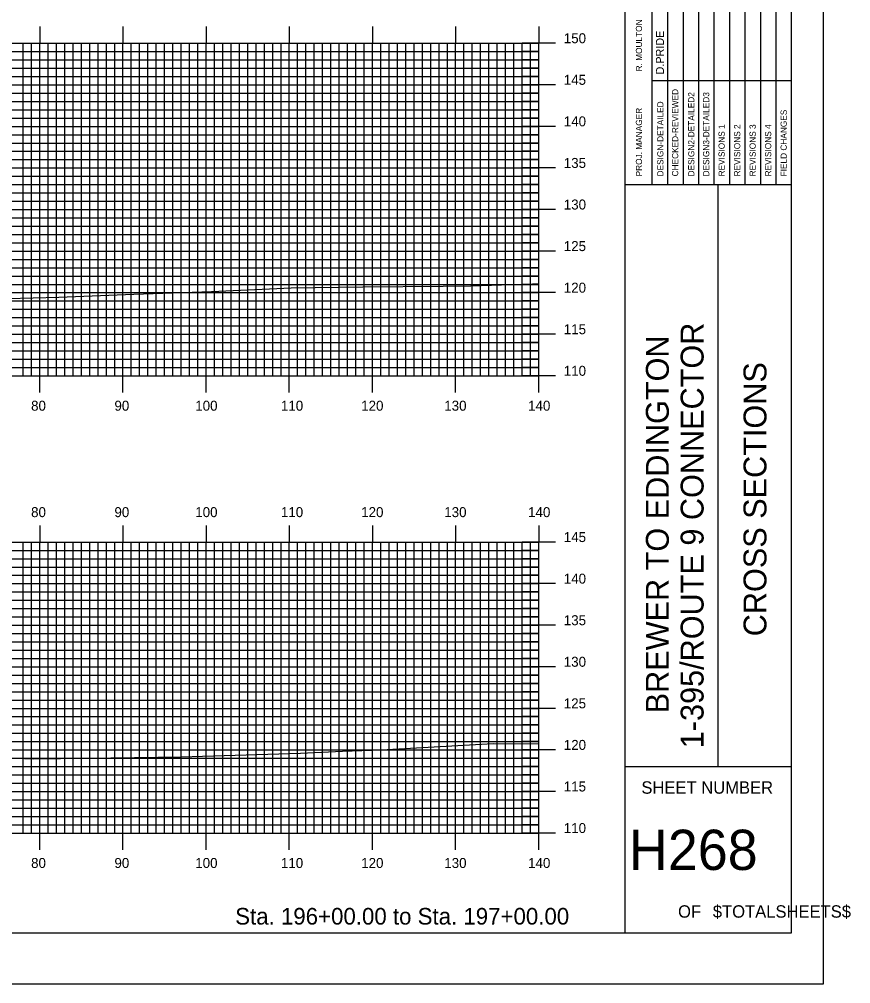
# Model space of a CAD drawing. Extents: x 1789730 to 1790074, y 442591 to 442811.
# Drawn here: x 1789973.7 to 1790073.7, y 442590.5 to 442706.6 of the extents above; entities that cross this region are included whole.
import ezdxf

# ---------------------------------------------------------------- set-up
doc = ezdxf.new("R2010")
doc.units = 0
for name, color, linetype in [('BORDER', 7, 'Continuous'), ('H_V ANNOTATION', 7, 'Continuous'), ('MAJOR', 7, 'Continuous'), ('MINOR', 7, 'Continuous'), ('PLOT BOUNDARY', 7, 'Continuous'), ('S_Roadway_Centerline', 7, 'Continuous')]:
    doc.layers.add(name, color=color, linetype=linetype)

msp = doc.modelspace()

# ---------------------------------------------------------------- linework, layer by layer
at = {"layer": 'BORDER'}
for p, q in [((1790046.58, 442596.67), (1790046.58, 442806.67)), ((1790046.58, 442686.67), (1790066.58, 442686.67)), ((1790057.76, 442616.67), (1790057.76, 442686.67)), ((1790046.58, 442616.67), (1790066.58, 442616.67))]:
    msp.add_line(p, q, dxfattribs=at)
msp.add_lwpolyline([(1789746.58, 442596.67), (1790066.58, 442596.67), (1790066.58, 442806.67), (1789746.58, 442806.67)], close=True, dxfattribs=at)
for points in [[(1790051.68, 442686.68), (1790051.68, 442721.67)], [(1790053.54, 442721.67), (1790053.54, 442686.68)], [(1790055.4, 442686.68), (1790055.4, 442721.67)], [(1790057.27, 442686.68), (1790057.27, 442721.67)], [(1790059.13, 442686.68), (1790059.13, 442721.67)], [(1790060.99, 442686.68), (1790060.99, 442721.67)], [(1790062.86, 442686.68), (1790062.86, 442721.67)], [(1790064.72, 442686.68), (1790064.72, 442721.67)], [(1790049.81, 442686.68), (1790049.81, 442720.26)], [(1790049.81, 442699.17), (1790066.58, 442699.17)]]:
    msp.add_lwpolyline(points, dxfattribs=at)
at = {"layer": 'MAJOR'}
for p, q in [((1789976.18, 442705.67), (1789976.18, 442703.67)), ((1789986.18, 442705.67), (1789986.18, 442703.67)), ((1789996.18, 442705.67), (1789996.18, 442703.67)), ((1790006.18, 442705.67), (1790006.18, 442703.67)), ((1790016.18, 442705.67), (1790016.18, 442703.67)), ((1790026.18, 442705.67), (1790026.18, 442703.67)), ((1790036.18, 442705.67), (1790036.18, 442703.67)), ((1789756.18, 442703.67), (1790036.18, 442703.67)), ((1789756.18, 442703.67), (1790036.18, 442703.67)), ((1789976.18, 442663.67), (1789976.18, 442703.67)), ((1789986.18, 442663.67), (1789986.18, 442703.67)), ((1789996.18, 442663.67), (1789996.18, 442703.67)), ((1790006.18, 442663.67), (1790006.18, 442703.67)), ((1790016.18, 442663.67), (1790016.18, 442703.67)), ((1790026.18, 442663.67), (1790026.18, 442703.67)), ((1790038.19, 442703.67), (1790034.18, 442703.67)), ((1790036.18, 442663.67), (1790036.18, 442703.67)), ((1790036.18, 442663.67), (1790036.18, 442703.67)), ((1789756.18, 442698.67), (1790036.18, 442698.67)), ((1790038.19, 442698.67), (1790034.18, 442698.67)), ((1789756.18, 442693.67), (1790036.18, 442693.67)), ((1790038.19, 442693.67), (1790034.18, 442693.67)), ((1789756.18, 442688.67), (1790036.18, 442688.67)), ((1790038.19, 442688.67), (1790034.18, 442688.67)), ((1789756.18, 442683.67), (1790036.18, 442683.67)), ((1790038.19, 442683.67), (1790034.18, 442683.67)), ((1789756.18, 442678.67), (1790036.18, 442678.67)), ((1790038.19, 442678.67), (1790034.18, 442678.67)), ((1789756.18, 442673.67), (1790036.18, 442673.67)), ((1790038.19, 442673.67), (1790034.18, 442673.67)), ((1789756.18, 442668.67), (1790036.18, 442668.67)), ((1790038.19, 442668.67), (1790034.18, 442668.67)), ((1789756.18, 442663.67), (1790036.18, 442663.67)), ((1789756.18, 442663.67), (1790036.18, 442663.67)), ((1789976.18, 442661.66), (1789976.18, 442663.67)), ((1789986.18, 442661.66), (1789986.18, 442663.67)), ((1789996.18, 442661.66), (1789996.18, 442663.67)), ((1790006.18, 442661.66), (1790006.18, 442663.67)), ((1790016.18, 442661.66), (1790016.18, 442663.67)), ((1790026.18, 442661.66), (1790026.18, 442663.67)), ((1790038.19, 442663.67), (1790034.18, 442663.67)), ((1790036.18, 442661.66), (1790036.18, 442663.67)), ((1789976.18, 442645.67), (1789976.18, 442643.67)), ((1789986.18, 442645.67), (1789986.18, 442643.67)), ((1789996.18, 442645.67), (1789996.18, 442643.67)), ((1790006.18, 442645.67), (1790006.18, 442643.67)), ((1790016.18, 442645.67), (1790016.18, 442643.67)), ((1790026.18, 442645.67), (1790026.18, 442643.67)), ((1790036.18, 442645.67), (1790036.18, 442643.67)), ((1789756.18, 442643.67), (1790036.18, 442643.67)), ((1789756.18, 442643.67), (1790036.18, 442643.67)), ((1789976.18, 442608.67), (1789976.18, 442643.67)), ((1789986.18, 442608.67), (1789986.18, 442643.67)), ((1789996.18, 442608.67), (1789996.18, 442643.67)), ((1790006.18, 442608.67), (1790006.18, 442643.67)), ((1790016.18, 442608.67), (1790016.18, 442643.67)), ((1790026.18, 442608.67), (1790026.18, 442643.67)), ((1790038.19, 442643.67), (1790034.18, 442643.67)), ((1790036.18, 442608.67), (1790036.18, 442643.67)), ((1790036.18, 442608.67), (1790036.18, 442643.67)), ((1789756.18, 442638.67), (1790036.18, 442638.67)), ((1790038.19, 442638.67), (1790034.18, 442638.67)), ((1789756.18, 442633.67), (1790036.18, 442633.67)), ((1790038.19, 442633.67), (1790034.18, 442633.67)), ((1789756.18, 442628.67), (1790036.18, 442628.67)), ((1790038.19, 442628.67), (1790034.18, 442628.67)), ((1789756.18, 442623.67), (1790036.18, 442623.67)), ((1790038.19, 442623.67), (1790034.18, 442623.67)), ((1789756.18, 442618.67), (1790036.18, 442618.67)), ((1790038.19, 442618.67), (1790034.18, 442618.67)), ((1789756.18, 442613.67), (1790036.18, 442613.67)), ((1790038.19, 442613.67), (1790034.18, 442613.67)), ((1789756.18, 442608.67), (1790036.18, 442608.67)), ((1789756.18, 442608.67), (1790036.18, 442608.67)), ((1789976.18, 442606.66), (1789976.18, 442608.67)), ((1789986.18, 442606.66), (1789986.18, 442608.67)), ((1789996.18, 442606.66), (1789996.18, 442608.67)), ((1790006.18, 442606.66), (1790006.18, 442608.67)), ((1790016.18, 442606.66), (1790016.18, 442608.67)), ((1790026.18, 442606.66), (1790026.18, 442608.67)), ((1790038.19, 442608.67), (1790034.18, 442608.67)), ((1790036.18, 442606.66), (1790036.18, 442608.67))]:
    msp.add_line(p, q, dxfattribs=at)
at = {"layer": 'MINOR'}
for p, q in [((1789974.18, 442663.67), (1789974.18, 442703.67)), ((1789975.18, 442663.67), (1789975.18, 442703.67)), ((1789977.18, 442663.67), (1789977.18, 442703.67)), ((1789978.18, 442663.67), (1789978.18, 442703.67)), ((1789979.18, 442663.67), (1789979.18, 442703.67)), ((1789980.18, 442663.67), (1789980.18, 442703.67)), ((1789981.18, 442663.67), (1789981.18, 442703.67)), ((1789982.18, 442663.67), (1789982.18, 442703.67)), ((1789983.18, 442663.67), (1789983.18, 442703.67)), ((1789984.18, 442663.67), (1789984.18, 442703.67)), ((1789985.18, 442663.67), (1789985.18, 442703.67)), ((1789987.18, 442663.67), (1789987.18, 442703.67)), ((1789988.18, 442663.67), (1789988.18, 442703.67)), ((1789989.18, 442663.67), (1789989.18, 442703.67)), ((1789990.18, 442663.67), (1789990.18, 442703.67)), ((1789991.18, 442663.67), (1789991.18, 442703.67)), ((1789992.18, 442663.67), (1789992.18, 442703.67)), ((1789993.18, 442663.67), (1789993.18, 442703.67)), ((1789994.18, 442663.67), (1789994.18, 442703.67)), ((1789995.18, 442663.67), (1789995.18, 442703.67)), ((1789997.18, 442663.67), (1789997.18, 442703.67)), ((1789998.18, 442663.67), (1789998.18, 442703.67)), ((1789999.18, 442663.67), (1789999.18, 442703.67)), ((1790000.18, 442663.67), (1790000.18, 442703.67)), ((1790001.18, 442663.67), (1790001.18, 442703.67)), ((1790002.18, 442663.67), (1790002.18, 442703.67)), ((1790003.18, 442663.67), (1790003.18, 442703.67)), ((1790004.18, 442663.67), (1790004.18, 442703.67)), ((1790005.18, 442663.67), (1790005.18, 442703.67)), ((1790007.18, 442663.67), (1790007.18, 442703.67)), ((1790008.18, 442663.67), (1790008.18, 442703.67)), ((1790009.18, 442663.67), (1790009.18, 442703.67)), ((1790010.18, 442663.67), (1790010.18, 442703.67)), ((1790011.18, 442663.67), (1790011.18, 442703.67)), ((1790012.18, 442663.67), (1790012.18, 442703.67)), ((1790013.18, 442663.67), (1790013.18, 442703.67)), ((1790014.18, 442663.67), (1790014.18, 442703.67)), ((1790015.18, 442663.67), (1790015.18, 442703.67)), ((1790017.18, 442663.67), (1790017.18, 442703.67)), ((1790018.18, 442663.67), (1790018.18, 442703.67)), ((1790019.18, 442663.67), (1790019.18, 442703.67)), ((1790020.18, 442663.67), (1790020.18, 442703.67)), ((1790021.18, 442663.67), (1790021.18, 442703.67)), ((1790022.18, 442663.67), (1790022.18, 442703.67)), ((1790023.18, 442663.67), (1790023.18, 442703.67)), ((1790024.18, 442663.67), (1790024.18, 442703.67)), ((1790025.18, 442663.67), (1790025.18, 442703.67)), ((1790027.18, 442663.67), (1790027.18, 442703.67)), ((1790028.18, 442663.67), (1790028.18, 442703.67)), ((1790029.18, 442663.67), (1790029.18, 442703.67)), ((1790030.18, 442663.67), (1790030.18, 442703.67)), ((1790031.18, 442663.67), (1790031.18, 442703.67)), ((1790032.18, 442663.67), (1790032.18, 442703.67)), ((1790033.18, 442663.67), (1790033.18, 442703.67)), ((1790034.18, 442663.67), (1790034.18, 442703.67)), ((1790035.18, 442663.67), (1790035.18, 442703.67)), ((1789756.18, 442702.67), (1790036.18, 442702.67)), ((1790036.18, 442702.67), (1790034.18, 442702.67)), ((1789756.18, 442701.67), (1790036.18, 442701.67)), ((1789756.18, 442700.67), (1790036.18, 442700.67)), ((1790036.18, 442701.67), (1790034.18, 442701.67)), ((1790036.18, 442700.67), (1790034.18, 442700.67)), ((1789756.18, 442699.67), (1790036.18, 442699.67)), ((1790036.18, 442699.67), (1790034.18, 442699.67)), ((1789756.18, 442697.67), (1790036.18, 442697.67)), ((1790036.18, 442697.67), (1790034.18, 442697.67)), ((1789756.18, 442696.67), (1790036.18, 442696.67)), ((1790036.18, 442696.67), (1790034.18, 442696.67)), ((1789756.18, 442695.67), (1790036.18, 442695.67)), ((1790036.18, 442695.67), (1790034.18, 442695.67)), ((1789756.18, 442694.67), (1790036.18, 442694.67)), ((1790036.18, 442694.67), (1790034.18, 442694.67)), ((1789756.18, 442692.67), (1790036.18, 442692.67)), ((1790036.18, 442692.67), (1790034.18, 442692.67)), ((1789756.18, 442691.67), (1790036.18, 442691.67)), ((1790036.18, 442691.67), (1790034.18, 442691.67)), ((1789756.18, 442690.67), (1790036.18, 442690.67)), ((1790036.18, 442690.67), (1790034.18, 442690.67)), ((1789756.18, 442689.67), (1790036.18, 442689.67)), ((1790036.18, 442689.67), (1790034.18, 442689.67)), ((1789756.18, 442687.67), (1790036.18, 442687.67)), ((1790036.18, 442687.67), (1790034.18, 442687.67)), ((1789756.18, 442686.67), (1790036.18, 442686.67)), ((1789756.18, 442685.67), (1790036.18, 442685.67)), ((1790036.18, 442686.67), (1790034.18, 442686.67)), ((1790036.18, 442685.67), (1790034.18, 442685.67)), ((1789756.18, 442684.67), (1790036.18, 442684.67)), ((1790036.18, 442684.67), (1790034.18, 442684.67)), ((1789756.18, 442682.67), (1790036.18, 442682.67)), ((1790036.18, 442682.67), (1790034.18, 442682.67)), ((1789756.18, 442681.67), (1790036.18, 442681.67)), ((1790036.18, 442681.67), (1790034.18, 442681.67)), ((1789756.18, 442680.67), (1790036.18, 442680.67)), ((1790036.18, 442680.67), (1790034.18, 442680.67)), ((1789756.18, 442679.67), (1790036.18, 442679.67)), ((1790036.18, 442679.67), (1790034.18, 442679.67)), ((1789756.18, 442677.67), (1790036.18, 442677.67)), ((1790036.18, 442677.67), (1790034.18, 442677.67)), ((1789756.18, 442676.67), (1790036.18, 442676.67)), ((1790036.18, 442676.67), (1790034.18, 442676.67)), ((1789756.18, 442675.67), (1790036.18, 442675.67)), ((1790036.18, 442675.67), (1790034.18, 442675.67)), ((1789756.18, 442674.67), (1790036.18, 442674.67)), ((1790036.18, 442674.67), (1790034.18, 442674.67)), ((1789756.18, 442672.67), (1790036.18, 442672.67)), ((1789756.18, 442671.67), (1790036.18, 442671.67)), ((1790036.18, 442672.67), (1790034.18, 442672.67)), ((1790036.18, 442671.67), (1790034.18, 442671.67)), ((1789756.18, 442670.67), (1790036.18, 442670.67)), ((1790036.18, 442670.67), (1790034.18, 442670.67)), ((1789756.18, 442669.67), (1790036.18, 442669.67)), ((1790036.18, 442669.67), (1790034.18, 442669.67)), ((1789756.18, 442667.67), (1790036.18, 442667.67)), ((1790036.18, 442667.67), (1790034.18, 442667.67)), ((1789756.18, 442666.67), (1790036.18, 442666.67)), ((1790036.18, 442666.67), (1790034.18, 442666.67)), ((1789756.18, 442665.67), (1790036.18, 442665.67)), ((1789756.18, 442664.67), (1790036.18, 442664.67)), ((1790036.18, 442665.67), (1790034.18, 442665.67)), ((1790036.18, 442664.67), (1790034.18, 442664.67)), ((1789756.18, 442642.67), (1790036.18, 442642.67)), ((1789974.18, 442608.67), (1789974.18, 442643.67)), ((1789975.18, 442608.67), (1789975.18, 442643.67)), ((1789977.18, 442608.67), (1789977.18, 442643.67)), ((1789978.18, 442608.67), (1789978.18, 442643.67)), ((1789979.18, 442608.67), (1789979.18, 442643.67)), ((1789980.18, 442608.67), (1789980.18, 442643.67)), ((1789981.18, 442608.67), (1789981.18, 442643.67)), ((1789982.18, 442608.67), (1789982.18, 442643.67)), ((1789983.18, 442608.67), (1789983.18, 442643.67)), ((1789984.18, 442608.67), (1789984.18, 442643.67)), ((1789985.18, 442608.67), (1789985.18, 442643.67)), ((1789987.18, 442608.67), (1789987.18, 442643.67)), ((1789988.18, 442608.67), (1789988.18, 442643.67)), ((1789989.18, 442608.67), (1789989.18, 442643.67)), ((1789990.18, 442608.67), (1789990.18, 442643.67)), ((1789991.18, 442608.67), (1789991.18, 442643.67)), ((1789992.18, 442608.67), (1789992.18, 442643.67)), ((1789993.18, 442608.67), (1789993.18, 442643.67)), ((1789994.18, 442608.67), (1789994.18, 442643.67)), ((1789995.18, 442608.67), (1789995.18, 442643.67)), ((1789997.18, 442608.67), (1789997.18, 442643.67)), ((1789998.18, 442608.67), (1789998.18, 442643.67)), ((1789999.18, 442608.67), (1789999.18, 442643.67)), ((1790000.18, 442608.67), (1790000.18, 442643.67)), ((1790001.18, 442608.67), (1790001.18, 442643.67)), ((1790002.18, 442608.67), (1790002.18, 442643.67)), ((1790003.18, 442608.67), (1790003.18, 442643.67)), ((1790004.18, 442608.67), (1790004.18, 442643.67)), ((1790005.18, 442608.67), (1790005.18, 442643.67)), ((1790007.18, 442608.67), (1790007.18, 442643.67)), ((1790008.18, 442608.67), (1790008.18, 442643.67)), ((1790009.18, 442608.67), (1790009.18, 442643.67)), ((1790010.18, 442608.67), (1790010.18, 442643.67)), ((1790011.18, 442608.67), (1790011.18, 442643.67)), ((1790012.18, 442608.67), (1790012.18, 442643.67)), ((1790013.18, 442608.67), (1790013.18, 442643.67)), ((1790014.18, 442608.67), (1790014.18, 442643.67)), ((1790015.18, 442608.67), (1790015.18, 442643.67)), ((1790017.18, 442608.67), (1790017.18, 442643.67)), ((1790018.18, 442608.67), (1790018.18, 442643.67)), ((1790019.18, 442608.67), (1790019.18, 442643.67)), ((1790020.18, 442608.67), (1790020.18, 442643.67)), ((1790021.18, 442608.67), (1790021.18, 442643.67)), ((1790022.18, 442608.67), (1790022.18, 442643.67)), ((1790023.18, 442608.67), (1790023.18, 442643.67)), ((1790024.18, 442608.67), (1790024.18, 442643.67)), ((1790025.18, 442608.67), (1790025.18, 442643.67)), ((1790027.18, 442608.67), (1790027.18, 442643.67)), ((1790028.18, 442608.67), (1790028.18, 442643.67)), ((1790029.18, 442608.67), (1790029.18, 442643.67)), ((1790030.18, 442608.67), (1790030.18, 442643.67)), ((1790031.18, 442608.67), (1790031.18, 442643.67)), ((1790032.18, 442608.67), (1790032.18, 442643.67)), ((1790033.18, 442608.67), (1790033.18, 442643.67)), ((1790034.18, 442608.67), (1790034.18, 442643.67)), ((1790036.18, 442642.67), (1790034.18, 442642.67)), ((1790035.18, 442608.67), (1790035.18, 442643.67)), ((1789756.18, 442641.67), (1790036.18, 442641.67)), ((1790036.18, 442641.67), (1790034.18, 442641.67)), ((1789756.18, 442640.67), (1790036.18, 442640.67)), ((1790036.18, 442640.67), (1790034.18, 442640.67)), ((1789756.18, 442639.67), (1790036.18, 442639.67)), ((1790036.18, 442639.67), (1790034.18, 442639.67)), ((1789756.18, 442637.67), (1790036.18, 442637.67)), ((1790036.18, 442637.67), (1790034.18, 442637.67)), ((1789756.18, 442636.67), (1790036.18, 442636.67)), ((1789756.18, 442635.67), (1790036.18, 442635.67)), ((1790036.18, 442636.67), (1790034.18, 442636.67)), ((1790036.18, 442635.67), (1790034.18, 442635.67)), ((1789756.18, 442634.67), (1790036.18, 442634.67)), ((1790036.18, 442634.67), (1790034.18, 442634.67)), ((1789756.18, 442632.67), (1790036.18, 442632.67)), ((1790036.18, 442632.67), (1790034.18, 442632.67)), ((1789756.18, 442631.67), (1790036.18, 442631.67)), ((1790036.18, 442631.67), (1790034.18, 442631.67)), ((1789756.18, 442630.67), (1790036.18, 442630.67)), ((1790036.18, 442630.67), (1790034.18, 442630.67)), ((1789756.18, 442629.67), (1790036.18, 442629.67)), ((1790036.18, 442629.67), (1790034.18, 442629.67)), ((1789756.18, 442627.67), (1790036.18, 442627.67)), ((1790036.18, 442627.67), (1790034.18, 442627.67)), ((1789756.18, 442626.67), (1790036.18, 442626.67)), ((1790036.18, 442626.67), (1790034.18, 442626.67)), ((1789756.18, 442625.67), (1790036.18, 442625.67)), ((1790036.18, 442625.67), (1790034.18, 442625.67)), ((1789756.18, 442624.67), (1790036.18, 442624.67)), ((1790036.18, 442624.67), (1790034.18, 442624.67)), ((1789756.18, 442622.67), (1790036.18, 442622.67)), ((1790036.18, 442622.67), (1790034.18, 442622.67)), ((1789756.18, 442621.67), (1790036.18, 442621.67)), ((1789756.18, 442620.67), (1790036.18, 442620.67)), ((1790036.18, 442621.67), (1790034.18, 442621.67)), ((1790036.18, 442620.67), (1790034.18, 442620.67)), ((1789756.18, 442619.67), (1790036.18, 442619.67)), ((1790036.18, 442619.67), (1790034.18, 442619.67)), ((1789756.18, 442617.67), (1790036.18, 442617.67)), ((1790036.18, 442617.67), (1790034.18, 442617.67)), ((1789756.18, 442616.67), (1790036.18, 442616.67)), ((1790036.18, 442616.67), (1790034.18, 442616.67)), ((1789756.18, 442615.67), (1790036.18, 442615.67)), ((1790036.18, 442615.67), (1790034.18, 442615.67)), ((1789756.18, 442614.67), (1790036.18, 442614.67)), ((1790036.18, 442614.67), (1790034.18, 442614.67)), ((1789756.18, 442612.67), (1790036.18, 442612.67)), ((1790036.18, 442612.67), (1790034.18, 442612.67)), ((1789756.18, 442611.67), (1790036.18, 442611.67)), ((1790036.18, 442611.67), (1790034.18, 442611.67)), ((1789756.18, 442610.67), (1790036.18, 442610.67)), ((1790036.18, 442610.67), (1790034.18, 442610.67)), ((1789756.18, 442609.67), (1790036.18, 442609.67)), ((1790036.18, 442609.67), (1790034.18, 442609.67))]:
    msp.add_line(p, q, dxfattribs=at)
at = {"layer": 'PLOT BOUNDARY'}
msp.add_lwpolyline([(1789730.4, 442590.55), (1790070.4, 442590.55), (1790070.4, 442810.55), (1789730.4, 442810.55)], close=True, dxfattribs=at)
at = {"layer": 'S_Roadway_Centerline'}
for points in [[(1789969.15, 442672.87), (1789978.48, 442673.13), (1789987.47, 442673.49), (1789996.83, 442673.81), (1790006.41, 442674.23), (1790015, 442674.38), (1790024.68, 442674.43), (1790028, 442674.48), (1790035.4, 442674.75), (1790036.18, 442674.78)], [(1789866.1, 442615.47), (1789877.12, 442615.72), (1789884.24, 442615.9), (1789891.9, 442616.02), (1789902.34, 442616.22), (1789913.55, 442616.33), (1789920.8, 442616.42), (1789927.99, 442616.59), (1789939.23, 442616.95), (1789948.34, 442617.44), (1789967.66, 442617.54), (1789973.16, 442617.66), (1789975.47, 442617.59), (1789981.87, 442617.69), (1789993.21, 442617.85), (1789995.72, 442617.91), (1790007.51, 442618.29), (1790012.57, 442618.51), (1790017.23, 442618.66), (1790030.7, 442619.44), (1790036.18, 442619.42)]]:
    msp.add_lwpolyline(points, dxfattribs=at)

# ---------------------------------------------------------------- texts
at = {"layer": 'BORDER'}
for s, height, p in [('R. MOULTON', 0.745, (1790048.59, 442700.28)), ('D.PRIDE', 0.969, (1790051.23, 442699.92)), ('CHECKED-REVIEWED', 0.7455, (1790052.94, 442687.65)), ('DESIGN2-DETAILED2', 0.7455, (1790054.88, 442687.65)), ('DESIGN3-DETAILED3', 0.7455, (1790056.67, 442687.65)), ('DESIGN-DETAILED', 0.7455, (1790051.16, 442687.65)), ('PROJ. MANAGER', 0.7455, (1790048.59, 442687.65)), ('FIELD CHANGES', 0.7455, (1790065.99, 442687.65)), ('REVISIONS 1', 0.7455, (1790058.53, 442687.65)), ('REVISIONS 2', 0.7455, (1790060.4, 442687.65)), ('REVISIONS 3', 0.7455, (1790062.26, 442687.65)), ('REVISIONS 4', 0.7455, (1790064.12, 442687.65)), ('1-395/ROUTE 9 CONNECTOR', 2.7557, (1790055.99, 442618.87)), ('BREWER TO EDDINGTON', 2.7557, (1790051.81, 442623.07)), ('CROSS SECTIONS', 2.7557, (1790063.55, 442632.34))]:
    msp.add_text(s, height=height, rotation=90, dxfattribs=at).set_placement(p)
for s, height, p in [('SHEET NUMBER', 1.4905, (1790048.51, 442613.4)), ('H268', 4.839, (1790047.02, 442604.23)), ('OF', 1.491, (1790052.92, 442598.49)), ('$TOTALSHEETS$', 1.4905, (1790057.1, 442598.49))]:
    msp.add_text(s, height=height, dxfattribs=at).set_placement(p)
at = {"layer": 'H_V ANNOTATION'}
for s, height, p in [('150', 1.2, (1790039.18, 442703.67)), ('145', 1.2, (1790039.18, 442698.67)), ('140', 1.2, (1790039.18, 442693.67)), ('135', 1.2, (1790039.18, 442688.67)), ('130', 1.2, (1790039.18, 442683.67)), ('125', 1.2, (1790039.18, 442678.67)), ('120', 1.2, (1790039.18, 442673.67)), ('115', 1.2, (1790039.18, 442668.67)), ('110', 1.2, (1790039.18, 442663.67)), ('80', 1.2, (1789975.13, 442659.47)), ('90', 1.2, (1789985.15, 442659.47)), ('100', 1.2, (1789994.87, 442659.47)), ('110', 1.2, (1790005.17, 442659.47)), ('120', 1.2, (1790014.82, 442659.47)), ('130', 1.2, (1790024.81, 442659.47)), ('140', 1.2, (1790034.89, 442659.47)), ('80', 1.2, (1789975.13, 442646.67)), ('90', 1.2, (1789985.15, 442646.67)), ('100', 1.2, (1789994.87, 442646.67)), ('110', 1.2, (1790005.17, 442646.67)), ('120', 1.2, (1790014.82, 442646.67)), ('130', 1.2, (1790024.81, 442646.67)), ('140', 1.2, (1790034.89, 442646.67)), ('145', 1.2, (1790039.18, 442643.67)), ('140', 1.2, (1790039.18, 442638.67)), ('135', 1.2, (1790039.18, 442633.67)), ('130', 1.2, (1790039.18, 442628.67)), ('125', 1.2, (1790039.18, 442623.67)), ('120', 1.2, (1790039.18, 442618.67)), ('115', 1.2, (1790039.18, 442613.67)), ('110', 1.2, (1790039.18, 442608.67)), ('80', 1.2, (1789975.13, 442604.47)), ('90', 1.2, (1789985.15, 442604.47)), ('100', 1.2, (1789994.87, 442604.47)), ('110', 1.2, (1790005.17, 442604.47)), ('120', 1.2, (1790014.82, 442604.47)), ('130', 1.2, (1790024.81, 442604.47)), ('140', 1.2, (1790034.89, 442604.47)), ('Sta. 196+00.00 to Sta. 197+00.00', 2.0004, (1789999.67, 442597.66))]:
    msp.add_text(s, height=height, dxfattribs=at).set_placement(p)

doc.saveas('drawing.dxf')
